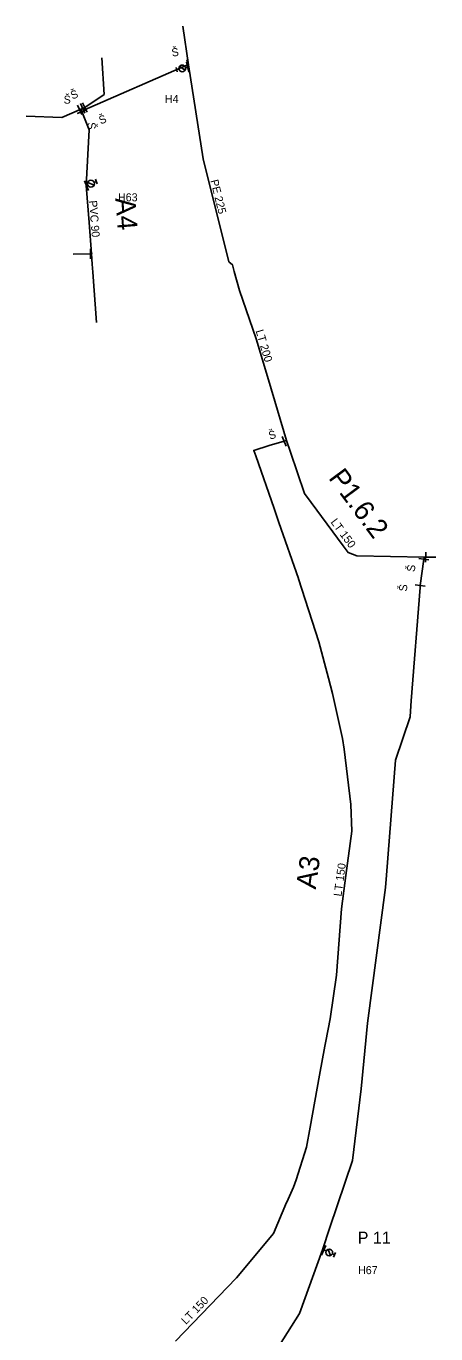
# Model space of a CAD drawing. Extents: x -569543 to -569081, y -1179531 to -1178244.
# Drawn here: x -569183.8 to -569081.3, y -1178571 to -1178244.3 of the extents above; entities that cross this region are included whole.
import ezdxf

# ---------------------------------------------------------------- set-up
doc = ezdxf.new("R2010")
doc.units = 0
for name, color, linetype in [('Vrstva 1', 7, 'Continuous'), ('Vrstva 15', 7, 'Continuous'), ('Vrstva 19', 7, 'Continuous'), ('Vrstva 25', 7, 'Continuous'), ('Vrstva 28', 7, 'Continuous'), ('Vrstva 29', 7, 'Continuous'), ('Vrstva 35', 7, 'Continuous')]:
    doc.layers.add(name, color=color, linetype=linetype)

# ---------------------------------------------------------------- blocks, each defined once
blk = doc.blocks.new('160')
at = {"layer": 'Vrstva 1'}
blk.add_circle((0, 0), 0.0458, dxfattribs=at)
blk = doc.blocks.new('147')
at = {"layer": 'Vrstva 1'}
blk.add_line((0, 1.27), (0, -1.27), dxfattribs=at)
blk = doc.blocks.new('133')
at = {"layer": 'Vrstva 1'}
for p, q in [((0.28, 0), (0, 0)), ((0.54, 0.58), (1.7, -0.58)), ((1.94, 0), (2.52, 0)), ((2.52, 0.58), (2.52, -0.58))]:
    blk.add_line(p, q, dxfattribs=at)
blk.add_circle((1.105, 0.003), 0.825, dxfattribs=at)
blk = doc.blocks.new('150')
at = {"layer": 'Vrstva 1'}
blk.add_line((0, 1.27), (0, -1.27), dxfattribs=at)

msp = doc.modelspace()

# ---------------------------------------------------------------- linework, layer by layer
at = {"layer": 'Vrstva 15'}
for p, q in [((-569143.37, -1178253.96), (-569143.195, -1178253.93)), ((-569170.11, -1178265.027), (-569170.41, -1178265.16)), ((-569170.11, -1178265.027), (-569169.64, -1178264.83)), ((-569169.88, -1178265.63), (-569170.11, -1178265.027)), ((-569169.64, -1178264.83), (-569169.403, -1178264.734)), ((-569169.099, -1178264.612), (-569169.403, -1178264.734)), ((-569167.428, -1178301.145), (-569167.688, -1178301.151)), ((-569118.688, -1178347.811), (-569119.24, -1178347.98)), ((-569083.85, -1178376.961), (-569084.265, -1178376.961))]:
    msp.add_line(p, q, dxfattribs=at)
for points in [[(-569164.88792, -1178252.16251), (-569164.27, -1178261.35), (-569169.099, -1178264.612)], [(-569169.403, -1178264.734), (-569169.217, -1178265.194), (-569143.562, -1178253.992), (-569143.37, -1178253.96)], [(-569170.41, -1178265.16), (-569174.883, -1178267.112), (-569183.79656, -1178266.76207)], [(-569167.428, -1178301.145), (-569168.045, -1178293.318), (-569168.769, -1178284.129), (-569168.062, -1178270.155), (-569169.88, -1178265.63)], [(-569167.688, -1178301.151), (-569172.00252, -1178301.25022)], [(-569166.15804, -1178318.34068), (-569167.087, -1178305.761), (-569167.234, -1178303.772), (-569167.428, -1178301.145)], [(-569126.8, -1178350.3), (-569126.325, -1178351.668), (-569121.774, -1178364.769), (-569120.555, -1178368.279), (-569115.686, -1178382.288), (-569115.65, -1178382.4), (-569110.57, -1178398.08), (-569108.147, -1178407.214), (-569107.15, -1178410.97), (-569104.63, -1178422.24), (-569104.245, -1178424.881), (-569102.558, -1178438.73), (-569102.29, -1178445.39), (-569103.793, -1178456.466), (-569104.93, -1178464.84), (-569106.157, -1178481.405), (-569106.153, -1178481.381), (-569107.716, -1178492.27), (-569107.721, -1178492.293), (-569108.829, -1178497.883), (-569109.071, -1178499.102), (-569109.075, -1178499.124), (-569110.391, -1178506.343), (-569112.765, -1178519.371), (-569113.668, -1178524.324), (-569113.676, -1178524.368), (-569116.27, -1178532.483), (-569116.873, -1178534.371), (-569118.606, -1178538.102), (-569118.644, -1178538.19), (-569121.94, -1178545.94), (-569131.19, -1178557.029), (-569131.23, -1178557.07), (-569146.439, -1178572.804)], [(-569119.24, -1178347.98), (-569122.982, -1178349.089), (-569126.8, -1178350.3)], [(-569081.29813, -1178376.96442), (-569083.85, -1178376.961)]]:
    msp.add_lwpolyline(points, dxfattribs=at)
at = {"layer": 'Vrstva 19'}
for p, q in [((-569085.217, -1178384.005), (-569084.332, -1178377.459)), ((-569084.332, -1178377.459), (-569084.265, -1178376.961))]:
    msp.add_line(p, q, dxfattribs=at)
for points in [[(-569143.195, -1178253.93), (-569144.5763, -1178244.28364)], [(-569131.752, -1178305.567), (-569132.21, -1178303.89), (-569133.087, -1178303.14), (-569139.502, -1178277.41), (-569143.195, -1178253.93)], [(-569118.688, -1178347.811), (-569123.197, -1178332.631), (-569126.23, -1178322.42), (-569130.446, -1178310.344), (-569131.752, -1178305.567)], [(-569084.265, -1178376.961), (-569101.073, -1178376.616), (-569103.239, -1178375.779), (-569104.475, -1178374.109), (-569112.511, -1178363.256), (-569114.146, -1178361.048), (-569117.698, -1178350.696), (-569118.688, -1178347.811)], [(-569126.848, -1178583.932), (-569115.399, -1178565.903), (-569109.69, -1178549.99), (-569107.811, -1178544.443), (-569102.14, -1178527.7), (-569102.141, -1178527.71), (-569099.966, -1178509.801), (-569099.96, -1178509.75), (-569098.39, -1178493.34), (-569093.92, -1178459.46), (-569093.676, -1178456.401), (-569091.39, -1178427.68), (-569087.77, -1178416.85), (-569087.76, -1178416.717), (-569087.461, -1178412.874), (-569085.259, -1178384.549), (-569085.217, -1178384.005)]]:
    msp.add_lwpolyline(points, dxfattribs=at)
at = {"layer": 'Vrstva 25'}
for p, q in [((-569168.769, -1178284.134), (-569168.633, -1178284.093)), ((-569109.69, -1178549.99), (-569109.026, -1178550.202))]:
    msp.add_line(p, q, dxfattribs=at)
msp.add_lwpolyline([(-569143.108, -1178254.453), (-569143.42, -1178254.52), (-569143.646, -1178254.572)], dxfattribs=at)

# ---------------------------------------------------------------- block references
for name, p, xscale, yscale, rotation in [('133', (-569143.646, -1178254.572), 1.0045862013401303, 1.00458620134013, -166.82590933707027), ('150', (-569143.42, -1178254.52), 1.0045862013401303, 1.00458620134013, -166.82590933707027), ('150', (-569168.701, -1178284.114), 1.035124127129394, 1.0351241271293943, 22.503654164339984), ('133', (-569168.633, -1178284.093), 1.035124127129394, 1.0351241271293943, 22.503654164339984), ('150', (-569109.358, -1178550.096), 1.0316957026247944, 1.0316957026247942, -23.584588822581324), ('133', (-569109.026, -1178550.202), 1.0316957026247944, 1.0316957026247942, -23.584588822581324)]:
    msp.add_blockref(name, p, dxfattribs=dict(at, xscale=xscale, yscale=yscale, rotation=rotation))
at = {"layer": 'Vrstva 29'}
for name, p, xscale, yscale, rotation in [('147', (-569143.37, -1178253.96), 1.00837761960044, 1.00837761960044, -168.3736213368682), ('160', (-569143.195, -1178253.93), 1.0092050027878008, 1.0092050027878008, -168.88308178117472), ('147', (-569169.88, -1178265.63), 0.999999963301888, 0.9999999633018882, 110.99999898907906), ('147', (-569170.41, -1178265.16), 1.022584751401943, 1.022584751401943, -154.18102569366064), ('147', (-569169.64, -1178264.83), 1.0275072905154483, 1.027507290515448, -155.31089431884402), ('160', (-569170.11, -1178265.027), 1.025136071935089, 1.0251360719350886, -154.74924162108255), ('147', (-569169.099, -1178264.612), 1.0106517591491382, 1.010651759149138, -151.83788415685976), ('160', (-569169.403, -1178264.734), 0.9999999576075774, 0.9999999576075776, 66.99999911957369), ('160', (-569167.428, -1178301.145), 0.9999999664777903, 0.9999999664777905, -132.99999806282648), ('160', (-569131.752, -1178305.567), 0.999999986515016, 0.9999999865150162, 105.00000012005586), ('147', (-569119.24, -1178347.98), 1.035124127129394, 1.0351241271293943, 22.503654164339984), ('160', (-569126.8, -1178350.3), 0.999999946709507, 0.999999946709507, 62.999999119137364), ('160', (-569118.688, -1178347.811), 0.9999999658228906, 0.9999999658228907, -117.99999982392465), ('147', (-569083.85, -1178376.961), 0.9999999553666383, 0.9999999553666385, -1.000000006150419), ('147', (-569084.332, -1178377.459), 0.9999999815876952, 0.9999999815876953, 82.0000004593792), ('160', (-569084.265, -1178376.961), 0.9999999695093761, 0.9999999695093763, 131.00000134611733), ('147', (-569085.217, -1178384.005), 1.0011216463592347, 1.0011216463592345, 83.41738977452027)]:
    msp.add_blockref(name, p, dxfattribs=dict(at, xscale=xscale, yscale=yscale, rotation=rotation))
at = {"layer": 'Vrstva 29', "rotation": 180}
msp.add_blockref('147', (-569167.688, -1178301.151), dxfattribs=at)

# ---------------------------------------------------------------- texts
at = {"layer": 'Vrstva 25'}
for s, height, p in [('H4', 1.999992, (-569149.086, -1178263.472)), ('H63', 1.999992, (-569160.823, -1178288.043)), ('P 11', 2.999988, (-569100.846, -1178548.462)), ('H67', 1.999992, (-569100.766, -1178556.072))]:
    msp.add_text(s, height=height, dxfattribs=at).set_placement(p)
at = {"layer": 'Vrstva 28'}
for rotation, p in [(9.09, (-569147.243, -1178251.925)), (359.38, (-569174.425, -1178263.63)), (21.9, (-569172.219, -1178262.628)), (275.01, (-569168.481, -1178268.385)), (21.37, (-569165.144, -1178268.849)), (17.56, (-569122.79, -1178347.618)), (82.8, (-569086.598, -1178380.718)), (84.7, (-569088.565, -1178385.578))]:
    msp.add_text('Š', height=1.99999, rotation=rotation, dxfattribs=at).set_placement(p)
at = {"layer": 'Vrstva 35'}
for s, height, rotation, p in [('PE 225', 1.999992, 284, (-569137.73, -1178282.861)), ('PVC 90', 1.999992, 274.51, (-569168.07, -1178287.903)), ('A4', 4.99998, 274.51, (-569161.5, -1178287.284)), ('LT 200', 1.999992, 286.54, (-569126.408, -1178320.41)), ('P1.6.2', 4.99998, 306.52, (-569108.314, -1178357.164)), ('LT 150', 1.999992, 306.52, (-569107.733, -1178368.197)), ('A3', 4.999974, 82.27, (-569111.348, -1178460.042)), ('LT 150', 1.999986, 82.27, (-569104.917, -1178461.778)), ('LT 150', 1.999992, 45.97, (-569143.804, -1178568.784))]:
    msp.add_text(s, height=height, rotation=rotation, dxfattribs=at).set_placement(p)

doc.saveas('drawing.dxf')
